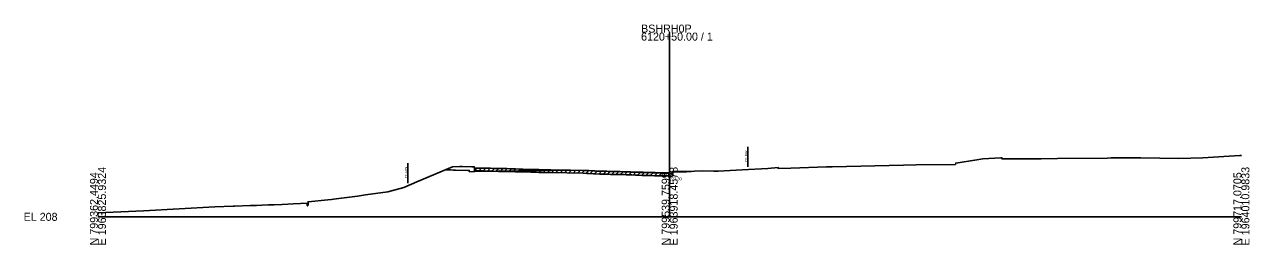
# Model space of a CAD drawing. Extents: x -26 to 1986619, y -10 to 827846.
# Drawn here: x -25.7 to 402.8, y 490.3 to 567.3 of the extents above; entities that cross this region are included whole.
import ezdxf

# ---------------------------------------------------------------- set-up
doc = ezdxf.new("R2010")
doc.units = 0
for name, color, linetype in [('Default', 7, 'Continuous'), ('RD_EX_Road', 7, 'Continuous'), ('RD_PD_ALT5_LnLine', 7, 'Continuous'), ('RD_PD_ALT5_TrvlWay', 7, 'Continuous'), ('RD_PD_PaveDit', 7, 'Continuous'), ('RD_Sketch2', 7, 'Continuous'), ('RD_XS_ExRW', 7, 'Continuous')]:
    doc.layers.add(name, color=color, linetype=linetype)

msp = doc.modelspace()

# ---------------------------------------------------------------- linework, layer by layer
at = {"layer": 'RD_EX_Road'}
for p, q in [((200, 500), (200, 564.49)), ((0, 500), (200, 500)), ((200, 500), (400, 500))]:
    msp.add_line(p, q, dxfattribs=at)
at = {"layer": 'RD_PD_ALT5_LnLine'}
msp.add_lwpolyline([(0.06, 501.36), (15.93, 502.14), (40.9, 503.45), (47.26, 503.75), (47.79, 503.74), (53.22, 503.99), (53.73, 503.98), (55.45, 504.02), (57.37, 504.08), (59.65, 504.17), (61.14, 504.24), (61.61, 504.25), (64.49, 504.37), (68.35, 504.55), (73.4, 504.83), (73.52, 505.28), (80.37, 505.96), (81.65, 506.11), (82.36, 506.21), (90.78, 507.29), (93.65, 507.65), (101.38, 508.78), (107.04, 510.25), (111.59, 512.21), (124.04, 517.52), (126.65, 517.63), (127.38, 517.61), (130.76, 517.56), (131.62, 517.54), (131.72, 517.09), (131.96, 517.07), (132.71, 517.08), (133.13, 517.08), (134.53, 517.05), (135.31, 517.03), (137.38, 516.98), (138.51, 516.96), (140.18, 516.92), (140.71, 516.91), (142.98, 516.87), (144.13, 516.84), (144.66, 516.83), (146.09, 516.78), (147.74, 516.73), (148.59, 516.7), (151.47, 516.62), (153.3, 516.58), (154.24, 516.56), (157.05, 516.5), (157.85, 516.47), (158.44, 516.5), (169.72, 516.23), (170.97, 516.2), (171.71, 516.16), (173.35, 516.07), (174.03, 516.03), (175.57, 515.98), (176.84, 515.94), (177.42, 515.93), (178.54, 515.89), (179.29, 515.87), (179.67, 515.86), (182.15, 515.82), (182.66, 515.81), (183.96, 515.76), (184.84, 515.73), (185.3, 515.71), (186.75, 515.65), (188.1, 515.6), (189.34, 515.56), (190.36, 515.52), (190.9, 515.51), (192.21, 515.47), (193.72, 515.43), (194.72, 515.4), (196.6, 515.35), (196.92, 515.35), (197.31, 515.34), (199.54, 515.31), (200.19, 515.29), (200.54, 515.26), (201.01, 515.21), (201.12, 515.27), (201.22, 515.76), (204.98, 515.76), (205.88, 515.76), (208.73, 516.03), (211.57, 516.12), (215.48, 515.97), (216.93, 516.03), (225.32, 516.45), (234.36, 516.95), (237.9, 517.31), (238, 516.86), (242.35, 516.98), (254.85, 517.52), (256.84, 517.56), (281.76, 518.09), (286.18, 518.19), (299.96, 518.37), (300.06, 518.83), (307.43, 519.96), (309.57, 520.29), (315.81, 520.68), (316.16, 520.7), (316.26, 520.25), (316.95, 520.26), (329.92, 520.32), (335.67, 520.42), (353.19, 520.58), (354.41, 520.61), (364.82, 520.69), (378.15, 520.43), (386.57, 520.67), (399.43, 521.5), (400, 521.5)], dxfattribs=at)
at = {"layer": 'RD_PD_PaveDit'}
for p, q in [((131.72, 516.09), (131.72, 517.09)), ((131.72, 516.09), (132.71, 517.08)), ((131.72, 516.09), (131.96, 516.07)), ((131.96, 516.07), (132.71, 516.08)), ((132.71, 516.08), (133.13, 516.08)), ((133.13, 516.08), (134.53, 516.05)), ((133.22, 516.08), (134.2, 517.06)), ((134.53, 516.05), (135.31, 516.03)), ((134.72, 516.05), (135.7, 517.02)), ((135.31, 516.03), (137.38, 515.98)), ((136.22, 516.01), (137.2, 516.99)), ((137.38, 515.98), (138.51, 515.96)), ((137.72, 515.97), (138.7, 516.95)), ((138.51, 515.96), (140.18, 515.92)), ((139.22, 515.94), (140.2, 516.92)), ((140.18, 515.92), (140.71, 515.91)), ((140.71, 515.91), (142.98, 515.87)), ((140.72, 515.91), (141.7, 516.89)), ((142.22, 515.88), (143.2, 516.86)), ((142.98, 515.87), (144.13, 515.84)), ((143.72, 515.85), (144.7, 516.83)), ((144.13, 515.84), (144.66, 515.83)), ((144.66, 515.83), (146.09, 515.78)), ((145.22, 515.81), (146.19, 516.78)), ((146.09, 515.78), (147.74, 515.73)), ((146.72, 515.76), (147.69, 516.73)), ((147.74, 515.73), (148.59, 515.7)), ((148.22, 515.71), (149.19, 516.68)), ((148.59, 515.7), (151.47, 515.62)), ((149.72, 515.67), (150.69, 516.64)), ((151.22, 515.62), (152.2, 516.6)), ((151.47, 515.62), (153.3, 515.58)), ((152.72, 515.59), (153.7, 516.57)), ((153.3, 515.58), (154.24, 515.56)), ((154.22, 515.56), (155.2, 516.54)), ((154.24, 515.56), (157.05, 515.5)), ((155.72, 515.53), (156.7, 516.51)), ((157.05, 515.5), (157.85, 515.47)), ((157.22, 515.49), (158.22, 516.49)), ((157.85, 515.47), (158.44, 515.5)), ((158.44, 515.5), (169.72, 515.23)), ((158.72, 515.49), (159.7, 516.47)), ((160.22, 515.46), (161.2, 516.44)), ((161.72, 515.42), (162.7, 516.4)), ((163.22, 515.39), (164.2, 516.36)), ((164.72, 515.35), (165.7, 516.33)), ((166.22, 515.31), (167.2, 516.29)), ((167.72, 515.28), (168.7, 516.26)), ((169.22, 515.24), (170.2, 516.22)), ((169.72, 515.23), (170.97, 515.2)), ((170.72, 515.21), (171.68, 516.16)), ((170.97, 515.2), (171.71, 515.16)), ((171.71, 515.16), (173.35, 515.07)), ((172.22, 515.13), (173.17, 516.08)), ((173.35, 515.07), (174.03, 515.03)), ((173.72, 515.05), (174.68, 516.01)), ((174.03, 515.03), (175.57, 514.98)), ((175.22, 514.99), (176.19, 515.96)), ((175.57, 514.98), (176.84, 514.94)), ((176.72, 514.95), (177.69, 515.92)), ((176.84, 514.94), (177.42, 514.93)), ((177.42, 514.93), (178.54, 514.89)), ((178.22, 514.9), (179.19, 515.87)), ((178.54, 514.89), (179.29, 514.87)), ((179.29, 514.87), (179.67, 514.86)), ((179.67, 514.86), (182.15, 514.82)), ((179.72, 514.86), (180.71, 515.84)), ((181.22, 514.83), (182.21, 515.81)), ((182.15, 514.82), (182.66, 514.81)), ((182.66, 514.81), (183.96, 514.76)), ((182.72, 514.81), (183.69, 515.77)), ((183.96, 514.76), (184.84, 514.73)), ((184.22, 514.75), (185.18, 515.72)), ((184.84, 514.73), (185.3, 514.71)), ((185.3, 514.71), (186.75, 514.65)), ((185.72, 514.69), (186.68, 515.66)), ((186.75, 514.65), (188.1, 514.6)), ((187.22, 514.63), (188.18, 515.6)), ((188.1, 514.6), (189.34, 514.56)), ((188.72, 514.58), (189.69, 515.54)), ((189.34, 514.56), (190.36, 514.52)), ((190.22, 514.53), (191.19, 515.5)), ((190.36, 514.52), (190.9, 514.51)), ((190.9, 514.51), (192.21, 514.47)), ((191.72, 514.48), (192.7, 515.46)), ((192.21, 514.47), (193.72, 514.43)), ((193.22, 514.44), (194.2, 515.42)), ((193.72, 514.43), (194.72, 514.4)), ((194.72, 514.4), (195.7, 515.38)), ((194.72, 514.4), (196.6, 514.35)), ((196.22, 514.36), (197.2, 515.34)), ((196.6, 514.35), (196.92, 514.35)), ((196.92, 514.35), (197.31, 514.34)), ((197.31, 514.34), (199.54, 514.31)), ((197.72, 514.34), (198.71, 515.32)), ((199.22, 514.31), (200.2, 515.29)), ((199.54, 514.31), (200.19, 514.29)), ((200.19, 514.29), (200.54, 514.26)), ((200.54, 514.26), (201.01, 514.21)), ((201.01, 514.21), (201.12, 514.5)), ((201.12, 515.5), (201.12, 514.5)), ((73.23, 503.82), (73.23, 504.82)), ((73.23, 503.82), (73.4, 503.83)), ((73.4, 503.83), (73.52, 504.28)), ((73.52, 505.28), (73.52, 504.28))]:
    msp.add_line(p, q, dxfattribs=at)
at = {"layer": 'RD_Sketch2'}
msp.add_lwpolyline([(121.43, 516.45), (121.53, 516.45), (122.1, 516.44), (122.6, 516.42), (123.34, 516.41), (124.35, 516.38), (125.06, 516.36), (129.39, 516.26), (129.9, 516.26), (129.98, 515.75), (131.41, 515.85), (131.9, 515.86), (163.42, 516.34), (165.27, 516.3), (194.95, 515.56), (199.54, 515.43), (200, 515.39), (200.93, 515.32), (201.01, 515.82), (201.5, 515.82), (202.26, 515.83), (206.41, 515.89), (207.4, 515.91), (207.55, 515.83)], dxfattribs=at)
at = {"layer": 'RD_XS_ExRW'}
for p, q in [((227.36, 517.56), (227.36, 524.56)), ((108.39, 511.84), (108.39, 518.84))]:
    msp.add_line(p, q, dxfattribs=at)

# ---------------------------------------------------------------- texts
at = {"layer": 'Default'}
msp.add_text('-', height=0.0001, dxfattribs=at).set_placement((0, 500))
at = {"layer": 'RD_EX_Road'}
for s, p in [('BSHRH0P', (190, 564.49)), ('6120+50.00 / 1', (190, 561.69)), ('EL 208', (-26, 498.6))]:
    msp.add_text(s, height=2.8, dxfattribs=at).set_placement(p)
for s, p in [('N 799362.4494', (0, 490)), ('E 1963825.9324', (2.8, 490)), ('N 799539.7599', (200, 490)), ('E 1963918.4578', (202.8, 490)), ('N 799717.0705', (400, 490)), ('E 1964010.9833', (402.8, 490))]:
    msp.add_text(s, height=2.8, rotation=90, dxfattribs=at).set_placement(p)
at = {"layer": 'RD_PD_ALT5_TrvlWay'}
msp.add_text('223.30', height=1, dxfattribs=at).set_placement((200, 512.8))
at = {"layer": 'RD_XS_ExRW'}
for p in [(227.1, 519.24), (108.14, 513.51)]:
    msp.add_text('EX. R/W ', height=0.75, rotation=90, dxfattribs=at).set_placement(p)

doc.saveas('drawing.dxf')
